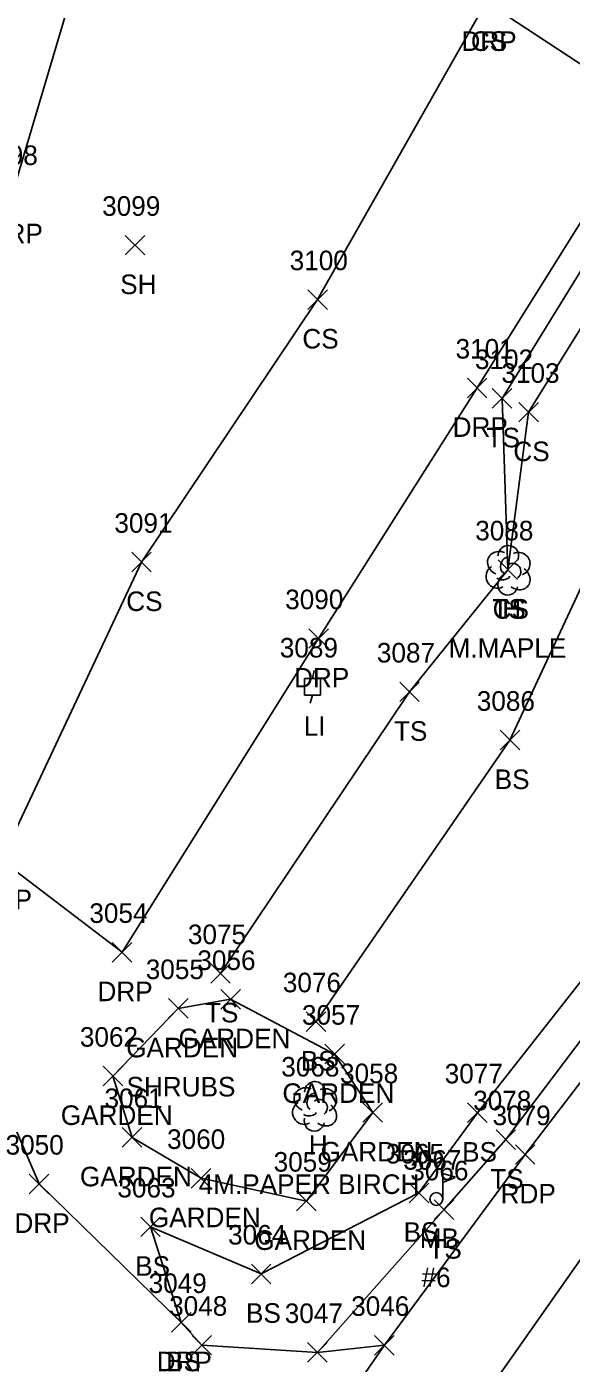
# Model space of a CAD drawing. Extents: x 1520648 to 1523413, y 732854 to 735518.
# Drawn here: x 1521729.4 to 1521785.1, y 733315.9 to 733452.5 of the extents above; entities that cross this region are included whole.
import ezdxf

# ---------------------------------------------------------------- set-up
doc = ezdxf.new("R2010")
doc.units = 0
for name, color, linetype in [('L_A', 7, 'Continuous'), ('L_C', 7, 'Continuous'), ('L_I', 7, 'Continuous'), ('L_TIC', 7, 'Continuous'), ('LAPB', 7, 'Continuous'), ('LELB', 7, 'Continuous'), ('LMB', 7, 'Continuous'), ('LTD', 7, 'Continuous'), ('P_A', 7, 'Continuous'), ('P_I', 7, 'Continuous'), ('P_TIC', 7, 'Continuous'), ('PET', 7, 'Continuous'), ('PRC', 7, 'Continuous'), ('R_A', 7, 'Continuous'), ('R_I', 7, 'Continuous'), ('R_TIC', 7, 'Continuous'), ('RDP', 7, 'Continuous'), ('U_A', 7, 'Continuous'), ('U_I', 7, 'Continuous'), ('ULP', 7, 'Continuous')]:
    doc.layers.add(name, color=color, linetype=linetype)

msp = doc.modelspace()

# ---------------------------------------------------------------- linework, layer by layer
at = {"layer": 'L_TIC'}
for points in [[(1521739.48, 733429.19), (1521741.48, 733431.19)], [(1521741.48, 733429.19), (1521739.48, 733431.19)], [(1521758.17, 733423.63), (1521760.17, 733425.63)], [(1521760.17, 733423.63), (1521758.17, 733425.63)], [(1521777.03, 733413.53), (1521779.03, 733415.53)], [(1521779.03, 733413.53), (1521777.03, 733415.53)], [(1521779.75, 733412.12), (1521781.75, 733414.12)], [(1521781.75, 733412.12), (1521779.75, 733414.12)], [(1521740.15, 733396.8), (1521742.15, 733398.8)], [(1521742.15, 733396.8), (1521740.15, 733398.8)], [(1521777.63, 733396.02), (1521779.63, 733398.02)], [(1521779.63, 733396.02), (1521777.63, 733398.02)], [(1521777.63, 733396.02), (1521779.63, 733398.02)], [(1521779.63, 733396.02), (1521777.63, 733398.02)], [(1521767.57, 733383.54), (1521769.57, 733385.54)], [(1521769.57, 733383.54), (1521767.57, 733385.54)], [(1521777.84, 733378.61), (1521779.84, 733380.61)], [(1521779.84, 733378.61), (1521777.84, 733380.61)], [(1521748.24, 733354.76), (1521750.24, 733356.76)], [(1521750.24, 733354.76), (1521748.24, 733356.76)], [(1521743.92, 733351.19), (1521745.92, 733353.19)], [(1521745.92, 733351.19), (1521743.92, 733353.19)], [(1521743.92, 733351.19), (1521745.92, 733353.19)], [(1521745.92, 733351.19), (1521743.92, 733353.19)], [(1521749.27, 733352.12), (1521751.27, 733354.12)], [(1521751.27, 733352.12), (1521749.27, 733354.12)], [(1521758.01, 733349.84), (1521760.01, 733351.84)], [(1521760.01, 733349.84), (1521758.01, 733351.84)], [(1521759.91, 733346.53), (1521761.91, 733348.53)], [(1521761.91, 733346.53), (1521759.91, 733348.53)], [(1521737.23, 733344.28), (1521739.23, 733346.28)], [(1521739.23, 733344.28), (1521737.23, 733346.28)], [(1521737.23, 733344.28), (1521739.23, 733346.28)], [(1521739.23, 733344.28), (1521737.23, 733346.28)], [(1521763.8, 733340.55), (1521765.8, 733342.55)], [(1521765.8, 733340.55), (1521763.8, 733342.55)], [(1521774.51, 733340.53), (1521776.51, 733342.53)], [(1521776.51, 733340.53), (1521774.51, 733342.53)], [(1521739.19, 733338.01), (1521741.19, 733340.01)], [(1521741.19, 733338.01), (1521739.19, 733340.01)], [(1521777.42, 733337.78), (1521779.42, 733339.78)], [(1521779.42, 733337.78), (1521777.42, 733339.78)], [(1521746.24, 733333.83), (1521748.24, 733335.83)], [(1521748.24, 733333.83), (1521746.24, 733335.83)], [(1521768.53, 733332.34), (1521770.53, 733334.34)], [(1521770.53, 733332.34), (1521768.53, 733334.34)], [(1521757.02, 733331.51), (1521759.02, 733333.51)], [(1521759.02, 733331.51), (1521757.02, 733333.51)], [(1521771.09, 733330.62), (1521773.09, 733332.62)], [(1521773.09, 733330.62), (1521771.09, 733332.62)], [(1521741.07, 733328.87), (1521743.07, 733330.87)], [(1521743.07, 733328.87), (1521741.07, 733330.87)], [(1521752.4, 733324.06), (1521754.4, 733326.06)], [(1521754.4, 733324.06), (1521752.4, 733326.06)], [(1521744.22, 733319.11), (1521746.22, 733321.11)], [(1521746.22, 733319.11), (1521744.22, 733321.11)], [(1521758.15, 733316.04), (1521760.15, 733318.04)], [(1521760.15, 733316.04), (1521758.15, 733318.04)]]:
    msp.add_lwpolyline(points, dxfattribs=at)
at = {"layer": 'LAPB'}
for points in [[(1521744.92, 733352.19), (1521750.27, 733353.12), (1521760.91, 733347.53), (1521764.8, 733341.55), (1521758.02, 733332.51), (1521747.24, 733334.83), (1521740.19, 733339.01), (1521738.23, 733345.28)], [(1521744.92, 733352.19), (1521738.23, 733345.28)]]:
    msp.add_lwpolyline(points, dxfattribs=at)
at = {"layer": 'LELB'}
for points in [[(1521759.01, 733350.84), (1521778.84, 733379.61), (1521791.35, 733406.4), (1521809.85, 733421.81), (1521821.29, 733449.95), (1521829.42, 733474.04), (1521816.98, 733499.02), (1521803.61, 733521.39), (1521760.13, 733541.49), (1521753.02, 733560.88), (1521736.69, 733577.42), (1521715.31, 733596.64)], [(1521749.24, 733355.76), (1521768.57, 733384.54), (1521778.63, 733397.02), (1521778.03, 733414.53), (1521789.55, 733433.16), (1521797.65, 733437.08), (1521807.29, 733437.92), (1521812.43, 733455.17), (1521816.31, 733477.33), (1521808.57, 733496.49), (1521793.28, 733514.64), (1521756.08, 733535.47), (1521746.24, 733557.11), (1521726.08, 733570.55), (1521703.63, 733583.19)], [(1521759.15, 733317.04), (1521772.09, 733331.62), (1521778.42, 733338.78), (1521798.75, 733365.67), (1521813.69, 733386.53), (1521833.96, 733414.18), (1521846.88, 733431.59), (1521864.41, 733458.07), (1521876.44, 733476.09), (1521887.28, 733496.86), (1521887.61, 733499.46), (1521888.35, 733509.55), (1521886.12, 733515.05), (1521875.14, 733547.35)], [(1521745.22, 733320.11), (1521742.07, 733329.87), (1521753.4, 733325.06), (1521769.53, 733333.34), (1521775.51, 733341.53), (1521796.31, 733367.94), (1521808.18, 733391.02), (1521828.43, 733418.45), (1521842.09, 733435.87), (1521859.18, 733460.44), (1521868.01, 733480.25), (1521878.13, 733498.03), (1521883.64, 733498.41), (1521879.84, 733511.18), (1521868.37, 733545.03)], [(1521726.82, 733367.33), (1521741.15, 733397.8), (1521759.17, 733424.63), (1521776.4, 733455.04)], [(1521778.63, 733397.02), (1521780.75, 733413.12), (1521789.58, 733427.31), (1521799.94, 733426.16), (1521807.29, 733437.92)]]:
    msp.add_lwpolyline(points, dxfattribs=at)
at = {"layer": 'LMB'}
for p, q in [((1521771.97, 733332.72), (1521771.97, 733335.32)), ((1521771.97, 733335.31), (1521773.26, 733334.93)), ((1521771.97, 733334.41), (1521773.25, 733334.92)), ((1521771.32, 733332.71), (1521771.32, 733332.71))]:
    msp.add_line(p, q, dxfattribs=at)
msp.add_circle((1521771.32, 733332.71), 0.656, dxfattribs=at)
at = {"layer": 'LTD'}
for p, q in [((1521778.63, 733397.02), (1521778.63, 733397.02)), ((1521778.63, 733397.02), (1521778.63, 733397.02)), ((1521758.84, 733342.23), (1521758.84, 733342.23)), ((1521758.84, 733342.23), (1521758.84, 733342.23))]:
    msp.add_line(p, q, dxfattribs=at)
for centre in [(1521778.68, 733398.45), (1521758.89, 733343.66)]:
    msp.add_arc(centre, 1.05, 335.5272, 180.9563, dxfattribs=at)
for centre, major_axis, ratio, start_param, end_param in [((1521777.84, 733397.69), (1.21, -0.51), 0.895232, 1.570796, 4.712389), ((1521778.42, 733397.48), (-0.208, -0.792), 0.645439, 3.141593, 6.283185), ((1521779.67, 733397.6), (-1.14, -0.48), 0.949671, 1.570796, 4.712389), ((1521777.55, 733396.31), (0.58, -1.04), 0.959034, 3.141593, 6.283185), ((1521779.13, 733396.85), (-0.5, 0.667), 0.989748, 3.141593, 6.283185), ((1521779.63, 733396.19), (-1.09, 0.79), 0.841452, 1.570796, 4.712389), ((1521778.63, 733395.52), (0.26, 1.06), 0.942809, 1.570796, 4.712389), ((1521778.17, 733396.27), (-0.625, -0.083), 0.423636, 0, 3.141593), ((1521758.05, 733342.89), (1.21, -0.51), 0.895232, 1.570796, 4.712389), ((1521759.88, 733342.81), (-1.14, -0.48), 0.949671, 1.570796, 4.712389), ((1521757.76, 733341.52), (0.58, -1.04), 0.959034, 3.141593, 6.283185), ((1521758.63, 733342.68), (-0.208, -0.792), 0.645439, 3.141593, 6.283185), ((1521759.34, 733342.06), (-0.5, 0.667), 0.989748, 3.141593, 6.283185), ((1521759.84, 733341.39), (-1.09, 0.79), 0.841452, 1.570796, 4.712389), ((1521758.84, 733340.73), (0.26, 1.06), 0.942809, 1.570796, 4.712389), ((1521758.38, 733341.48), (-0.625, -0.083), 0.423636, 0, 3.141593)]:
    msp.add_ellipse(centre, major_axis=major_axis, ratio=ratio, start_param=start_param, end_param=end_param, dxfattribs=at)
at = {"layer": 'P_TIC'}
for points in [[(1521779.4, 733336.26), (1521781.4, 733338.26)], [(1521781.4, 733336.26), (1521779.4, 733338.26)], [(1521765, 733316.77), (1521767, 733318.77)], [(1521767, 733316.77), (1521765, 733318.77)]]:
    msp.add_lwpolyline(points, dxfattribs=at)
at = {"layer": 'PET'}
msp.add_lwpolyline([(1521760.79, 733310.27), (1521766, 733317.77), (1521780.4, 733337.26), (1521801.02, 733364.18), (1521815.88, 733384.95), (1521835.85, 733412.69), (1521849.25, 733429.67), (1521867.5, 733456.15), (1521880.02, 733475.39), (1521889.73, 733495.65), (1521892.95, 733514.59)], dxfattribs=at)
at = {"layer": 'PRC'}
msp.add_lwpolyline([(1521770.1, 733303.86), (1521789.18, 733330.98), (1521810.63, 733359.66), (1521824.22, 733378.34), (1521845.61, 733407.68), (1521857.16, 733423.44), (1521877.35, 733449.78), (1521891.97, 733468.24), (1521903.82, 733481.12)], dxfattribs=at)
at = {"layer": 'R_TIC'}
for points in [[(1521774.49, 733414.6), (1521776.49, 733416.6)], [(1521776.49, 733414.6), (1521774.49, 733416.6)], [(1521758.27, 733388.99), (1521760.27, 733390.99)], [(1521760.27, 733388.99), (1521758.27, 733390.99)], [(1521738.16, 733356.93), (1521740.16, 733358.93)], [(1521740.16, 733356.93), (1521738.16, 733358.93)], [(1521729.68, 733333.25), (1521731.68, 733335.25)], [(1521731.68, 733333.25), (1521729.68, 733335.25)], [(1521744.22, 733319.11), (1521746.22, 733321.11)], [(1521746.22, 733319.11), (1521744.22, 733321.11)], [(1521746.32, 733316.78), (1521748.32, 733318.78)], [(1521748.32, 733316.78), (1521746.32, 733318.78)], [(1521758.15, 733316.04), (1521760.15, 733318.04)], [(1521760.15, 733316.04), (1521758.15, 733318.04)], [(1521765, 733316.77), (1521767, 733318.77)], [(1521767, 733316.77), (1521765, 733318.77)]]:
    msp.add_lwpolyline(points, dxfattribs=at)
at = {"layer": 'RDP'}
for points in [[(1521766, 733317.77), (1521759.15, 733317.04), (1521747.32, 733317.78), (1521745.22, 733320.11), (1521730.68, 733334.25), (1521725.41, 733346.47), (1521724.94, 733355.82), (1521726.82, 733367.33), (1521739.16, 733357.93), (1521759.27, 733389.99), (1521775.49, 733415.6), (1521793.24, 733444), (1521776.4, 733455.04), (1521760.93, 733467.25), (1521758.1, 733472.44), (1521748.94, 733490.42), (1521732.1, 733509.37), (1521713.69, 733523.9), (1521690.78, 733537.56)], [(1521678.96, 733392.35), (1521701.59, 733424.52), (1521714.94, 733443.08), (1521727.93, 733435.38), (1521734.93, 733458.92), (1521724.21, 733475.33), (1521709.2, 733487.68), (1521683.55, 733505.62), (1521674.22, 733511.48), (1521662.29, 733517.33), (1521649.85, 733521.14), (1521628.82, 733520.6), (1521627.26, 733520.31), (1521618.6, 733518.02), (1521610.73, 733513.2), (1521601.46, 733505.07), (1521592.79, 733495.19), (1521593.24, 733493.56)]]:
    msp.add_lwpolyline(points, dxfattribs=at)
at = {"layer": 'ULP'}
for p, q in [((1521758.81, 733386.72), (1521758.64, 733385.89)), ((1521757.81, 733384.22), (1521757.81, 733385.89)), ((1521757.81, 733385.89), (1521759.48, 733385.89)), ((1521758.64, 733385.05), (1521758.64, 733385.05)), ((1521759.48, 733385.89), (1521759.48, 733384.22)), ((1521759.48, 733384.22), (1521757.81, 733384.22)), ((1521758.39, 733383.39), (1521758.64, 733384.22))]:
    msp.add_line(p, q, dxfattribs=at)

# ---------------------------------------------------------------- texts
at = {"layer": 'L_A'}
for s, p in [('CS', (1521774.84, 733450.04)), ('SH', (1521738.97, 733425.19)), ('CS', (1521757.61, 733419.63)), ('TS', (1521776.44, 733409.53)), ('CS', (1521779.19, 733408.12)), ('CS', (1521739.59, 733392.8)), ('TS', (1521777.04, 733392.02)), ('CS', (1521777.07, 733392.02)), ('H', (1521778.06, 733392.02)), ('TS', (1521766.98, 733379.54)), ('BS', (1521777.28, 733374.61)), ('TS', (1521747.65, 733350.76)), ('GARDEN', (1521739.59, 733347.19)), ('GARDEN', (1521739.59, 733347.19)), ('GARDEN', (1521744.94, 733348.12)), ('BS', (1521757.45, 733345.84)), ('GARDEN', (1521755.57, 733342.53)), ('GARDEN', (1521732.9, 733340.28)), ('GARDEN', (1521732.9, 733340.28)), ('H', (1521758.27, 733337.23)), ('GARDEN', (1521759.47, 733336.55)), ('BS', (1521773.95, 733336.53)), ('GARDEN', (1521734.86, 733334.01)), ('TS', (1521776.83, 733333.78)), ('GARDEN', (1521741.91, 733329.83)), ('BS', (1521767.97, 733328.34)), ('GARDEN', (1521752.69, 733327.51)), ('MB', (1521769.62, 733327.71)), ('TS', (1521770.5, 733326.62)), ('BS', (1521740.51, 733324.87)), ('BS', (1521751.84, 733320.06)), ('BS', (1521743.67, 733315.11))]:
    msp.add_text(s, height=2, dxfattribs=at).set_placement(p)
at = {"layer": 'L_C'}
for s, p in [('M.MAPLE', (1521772.57, 733388.02)), ('SHRUBS', (1521739.62, 733343.19)), ('SHRUBS', (1521739.62, 733343.19)), ('4M.PAPER BIRCH', (1521747, 733333.23)), ('#6', (1521769.8, 733323.71))]:
    msp.add_text(s, height=2, dxfattribs=at).set_placement(p)
at = {"layer": 'L_I'}
for s, p in [('3099', (1521737.13, 733433.19)), ('3100', (1521756.31, 733427.63)), ('3102', (1521775.26, 733417.53)), ('3103', (1521777.97, 733416.12)), ('3091', (1521738.38, 733400.8)), ('3088', (1521775.29, 733400.02)), ('3088', (1521775.29, 733400.02)), ('3088', (1521775.29, 733400.02)), ('3087', (1521765.23, 733387.54)), ('3086', (1521775.45, 733382.61)), ('3075', (1521745.9, 733358.76)), ('3056', (1521746.87, 733356.12)), ('3055', (1521741.59, 733355.19)), ('3055', (1521741.59, 733355.19)), ('3076', (1521755.61, 733353.84)), ('3057', (1521757.57, 733350.53)), ('3062', (1521734.85, 733348.28)), ('3062', (1521734.85, 733348.28)), ('3068', (1521755.45, 733345.23)), ('3058', (1521761.46, 733344.55)), ('3077', (1521772.17, 733344.53)), ('3061', (1521737.37, 733342.01)), ('3078', (1521775.08, 733341.78)), ('3060', (1521743.77, 733337.83)), ('3065', (1521766.15, 733336.34)), ('3059', (1521754.67, 733335.51)), ('3067', (1521767.93, 733335.71)), ('3066', (1521768.65, 733334.62)), ('3063', (1521738.69, 733332.87)), ('3064', (1521750.01, 733328.06)), ('3049', (1521741.88, 733323.11)), ('3047', (1521755.81, 733320.04))]:
    msp.add_text(s, height=2, dxfattribs=at).set_placement(p)
at = {"layer": 'P_A'}
msp.add_text('RDP', height=2, dxfattribs=at).set_placement((1521777.89, 733332.26))
at = {"layer": 'P_I'}
for s, p in [('3079', (1521777.06, 733340.26)), ('3046', (1521762.6, 733320.77))]:
    msp.add_text(s, height=2, dxfattribs=at).set_placement(p)
at = {"layer": 'R_A'}
for p in [(1521773.88, 733450.04), (1521725.42, 733430.38), (1521772.98, 733410.6), (1521756.76, 733384.99), (1521724.31, 733362.33), (1521736.65, 733352.93), (1521728.16, 733329.25), (1521742.71, 733315.11)]:
    msp.add_text('DRP', height=2, dxfattribs=at).set_placement(p)
at = {"layer": 'R_I'}
for s, p in [('3098', (1521724.6, 733438.38)), ('3101', (1521773.28, 733418.6)), ('3090', (1521755.85, 733392.99)), ('3054', (1521735.82, 733360.93)), ('3050', (1521727.25, 733337.25)), ('3049', (1521741.88, 733323.11)), ('3048', (1521743.98, 733320.78)), ('3047', (1521755.81, 733320.04)), ('3046', (1521762.6, 733320.77))]:
    msp.add_text(s, height=2, dxfattribs=at).set_placement(p)
at = {"layer": 'U_A'}
msp.add_text('LI', height=2, dxfattribs=at).set_placement((1521757.75, 733380.05))
at = {"layer": 'U_I'}
msp.add_text('3089', height=2, dxfattribs=at).set_placement((1521755.3, 733388.05))

doc.saveas('drawing.dxf')
